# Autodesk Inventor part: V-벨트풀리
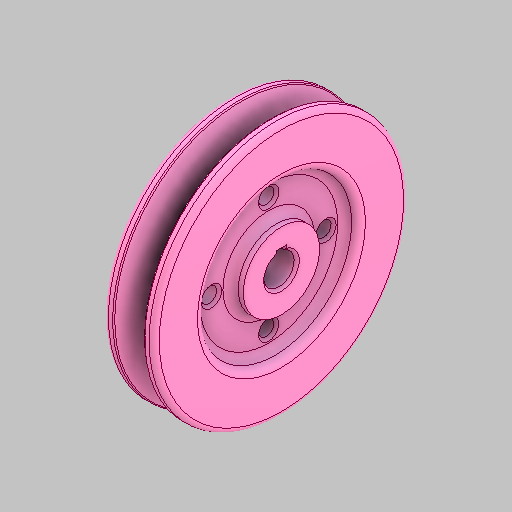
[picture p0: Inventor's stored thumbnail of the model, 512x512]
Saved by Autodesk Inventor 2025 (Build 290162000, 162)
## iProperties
Created: 2024-07
Part Number: V-벨트풀리
Material: 강철, 연강
Document SubType Name: Modeling
Designer: 현기
Density: 7.86 g/cm^3
Appearance: 기본값
Author: jhkim
Sending System: Autodesk Inventor 2025
Preprocessor: ST-DEVELOPER v20
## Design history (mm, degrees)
feature "솔리드1"
node "솔리드2"
